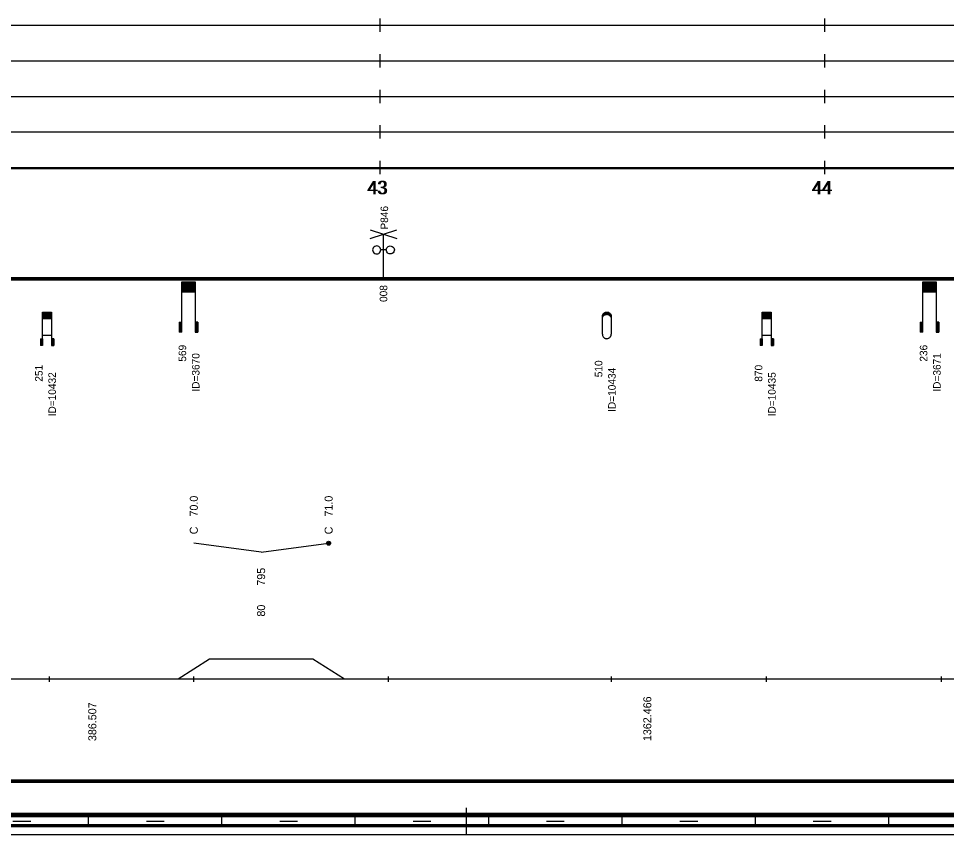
# Model space of a CAD drawing. Extents: x 2 to 10148, y 0 to 380.
# Drawn here: x 4519.3 to 4727.9, y 0 to 183.5 of the extents above; entities that cross this region are included whole.
import ezdxf

# ---------------------------------------------------------------- set-up
doc = ezdxf.new("R2010")
doc.units = 0
for name, color, linetype in [('CARA_S_OBJEKTY', 7, 'Continuous'), ('KRIV1_CARA', 7, 'Continuous'), ('KRIV1_TEXT', 7, 'Continuous'), ('OBJEKTY_TEXT', 7, 'Continuous'), ('OBJEKTY_TVAR', 7, 'Continuous'), ('RAM', 7, 'Continuous'), ('RYCHL_RASTR', 7, 'Continuous'), ('RYCHL_STAN', 7, 'Continuous'), ('STAN_CARA', 7, 'Continuous')]:
    doc.layers.add(name, color=color, linetype=linetype)

msp = doc.modelspace()

# ---------------------------------------------------------------- linework, layer by layer
for p, q in [((4526.17, 35.51), (4526.17, 34.32)), ((4558.59, 35.51), (4558.59, 34.32)), ((4602.42, 35.51), (4602.42, 34.32)), ((4652.55, 35.51), (4652.55, 34.32)), ((4687.39, 35.51), (4687.39, 34.32)), ((4726.73, 35.51), (4726.73, 34.32))]:
    msp.add_line(p, q)
at = {"layer": 'CARA_S_OBJEKTY'}
for p, q in [((4045.76, 125.25), (5128.6, 125.25)), ((4045.76, 125), (5128.6, 125)), ((4045.76, 124.75), (5128.6, 124.75))]:
    msp.add_line(p, q, dxfattribs=at)
at = {"layer": 'KRIV1_CARA'}
for p, q in [((4555.17, 35), (4562.17, 39.53)), ((4562.17, 39.53), (4585.45, 39.53)), ((4585.45, 39.53), (4592.55, 35)), ((4045.76, 35), (5128.6, 35))]:
    msp.add_line(p, q, dxfattribs=at)
at = {"layer": 'KRIV1_TEXT'}
for q in [(4558.67, 65.5), (4589, 65.5)]:
    msp.add_line((4573.81, 63.5), q, dxfattribs=at)
for radius in [0.45, 0.3, 0.15]:
    msp.add_circle((4589, 65.5), radius, dxfattribs=at)
at = {"layer": 'OBJEKTY_TVAR'}
for p, q in [((4598.34, 134), (4604.34, 136)), ((4598.34, 136), (4604.34, 134)), ((4601.34, 125), (4601.34, 135)), ((4598.93, 131.7), (4598.9, 131.46)), ((4599.02, 131.92), (4598.93, 131.7)), ((4599.17, 132.11), (4599.02, 131.92)), ((4599.36, 132.25), (4599.17, 132.11)), ((4599.58, 132.34), (4599.36, 132.25)), ((4599.81, 132.38), (4599.58, 132.34)), ((4600.05, 132.34), (4599.81, 132.38)), ((4600.27, 132.25), (4600.05, 132.34)), ((4600.46, 132.11), (4600.27, 132.25)), ((4600.6, 131.92), (4600.46, 132.11)), ((4600.69, 131.7), (4600.6, 131.92)), ((4600.72, 131.46), (4600.69, 131.7)), ((4601.96, 131.46), (4601.99, 131.7)), ((4601.99, 131.7), (4602.08, 131.92)), ((4602.08, 131.92), (4602.22, 132.11)), ((4602.22, 132.11), (4602.41, 132.25)), ((4602.41, 132.25), (4602.63, 132.34)), ((4602.63, 132.34), (4602.87, 132.38)), ((4602.87, 132.38), (4603.1, 132.34)), ((4603.1, 132.34), (4603.32, 132.25)), ((4603.32, 132.25), (4603.51, 132.11)), ((4603.51, 132.11), (4603.66, 131.92)), ((4603.66, 131.92), (4603.75, 131.7)), ((4603.75, 131.7), (4603.78, 131.46)), ((4598.9, 131.46), (4598.93, 131.23)), ((4598.93, 131.23), (4599.02, 131.01)), ((4599.02, 131.01), (4599.17, 130.82)), ((4599.17, 130.82), (4599.36, 130.67)), ((4599.36, 130.67), (4599.58, 130.58)), ((4599.58, 130.58), (4599.81, 130.55)), ((4599.81, 130.55), (4600.05, 130.58)), ((4600.05, 130.58), (4600.27, 130.67)), ((4600.27, 130.67), (4600.46, 130.82)), ((4600.46, 130.82), (4600.6, 131.01)), ((4600.6, 131.01), (4600.69, 131.23)), ((4600.69, 131.23), (4600.72, 131.46)), ((4601.96, 131.46), (4600.72, 131.46)), ((4601.99, 131.23), (4601.96, 131.46)), ((4602.08, 131.01), (4601.99, 131.23)), ((4602.22, 130.82), (4602.08, 131.01)), ((4602.41, 130.67), (4602.22, 130.82)), ((4602.63, 130.58), (4602.41, 130.67)), ((4602.87, 130.55), (4602.63, 130.58)), ((4603.1, 130.58), (4602.87, 130.55)), ((4603.32, 130.67), (4603.1, 130.58)), ((4603.51, 130.82), (4603.32, 130.67)), ((4603.66, 131.01), (4603.51, 130.82)), ((4603.75, 131.23), (4603.66, 131.01)), ((4603.78, 131.46), (4603.75, 131.23)), ((4555.96, 124.25), (4558.96, 124.25)), ((4555.96, 113), (4555.96, 124.25)), ((4555.96, 124.17), (4558.96, 124.17)), ((4555.96, 124.1), (4558.96, 124.1)), ((4555.96, 124.02), (4558.96, 124.02)), ((4555.96, 123.95), (4558.96, 123.95)), ((4555.96, 123.87), (4558.96, 123.87)), ((4555.96, 123.8), (4558.96, 123.8)), ((4555.96, 123.72), (4558.96, 123.72)), ((4555.96, 123.65), (4558.96, 123.65)), ((4555.96, 123.57), (4558.96, 123.57)), ((4555.96, 123.5), (4558.96, 123.5)), ((4555.96, 123.42), (4558.96, 123.42)), ((4555.96, 123.35), (4558.96, 123.35)), ((4555.96, 123.27), (4558.96, 123.27)), ((4555.96, 123.2), (4558.96, 123.2)), ((4558.96, 124.25), (4558.96, 113)), ((4722.65, 124.25), (4725.65, 124.25)), ((4722.65, 113), (4722.65, 124.25)), ((4722.65, 124.17), (4725.65, 124.17)), ((4722.65, 124.1), (4725.65, 124.1)), ((4722.65, 124.02), (4725.65, 124.02)), ((4722.65, 123.95), (4725.65, 123.95)), ((4722.65, 123.87), (4725.65, 123.87)), ((4722.65, 123.8), (4725.65, 123.8)), ((4722.65, 123.72), (4725.65, 123.72)), ((4722.65, 123.65), (4725.65, 123.65)), ((4722.65, 123.57), (4725.65, 123.57)), ((4722.65, 123.5), (4725.65, 123.5)), ((4722.65, 123.42), (4725.65, 123.42)), ((4722.65, 123.35), (4725.65, 123.35)), ((4722.65, 123.27), (4725.65, 123.27)), ((4722.65, 123.2), (4725.65, 123.2)), ((4725.65, 124.25), (4725.65, 113)), ((4555.96, 123.12), (4558.96, 123.12)), ((4555.96, 123.05), (4558.96, 123.05)), ((4555.96, 122.97), (4558.96, 122.97)), ((4555.96, 122.9), (4558.96, 122.9)), ((4555.96, 122.82), (4558.96, 122.82)), ((4555.96, 122.75), (4558.96, 122.75)), ((4555.96, 122.67), (4558.96, 122.67)), ((4555.96, 122.6), (4558.96, 122.6)), ((4555.96, 122.52), (4558.96, 122.52)), ((4555.96, 122.45), (4558.96, 122.45)), ((4555.96, 122.37), (4558.96, 122.37)), ((4555.96, 122.3), (4558.96, 122.3)), ((4555.96, 122.22), (4558.96, 122.22)), ((4555.96, 122.15), (4558.96, 122.15)), ((4555.96, 122.07), (4558.96, 122.07)), ((4722.65, 123.12), (4725.65, 123.12)), ((4722.65, 123.05), (4725.65, 123.05)), ((4722.65, 122.97), (4725.65, 122.97)), ((4722.65, 122.9), (4725.65, 122.9)), ((4722.65, 122.82), (4725.65, 122.82)), ((4722.65, 122.75), (4725.65, 122.75)), ((4722.65, 122.67), (4725.65, 122.67)), ((4722.65, 122.6), (4725.65, 122.6)), ((4722.65, 122.52), (4725.65, 122.52)), ((4722.65, 122.45), (4725.65, 122.45)), ((4722.65, 122.37), (4725.65, 122.37)), ((4722.65, 122.3), (4725.65, 122.3)), ((4722.65, 122.22), (4725.65, 122.22)), ((4722.65, 122.15), (4725.65, 122.15)), ((4722.65, 122.07), (4725.65, 122.07)), ((4524.67, 110), (4524.67, 117.5)), ((4524.67, 117.5), (4526.67, 117.5)), ((4524.67, 117.45), (4526.67, 117.45)), ((4524.67, 117.4), (4526.67, 117.4)), ((4524.67, 117.35), (4526.67, 117.35)), ((4524.67, 117.3), (4526.67, 117.3)), ((4524.67, 117.25), (4526.67, 117.25)), ((4524.67, 117.2), (4526.67, 117.2)), ((4524.67, 117.15), (4526.67, 117.15)), ((4524.67, 117.1), (4526.67, 117.1)), ((4524.67, 117.05), (4526.67, 117.05)), ((4524.67, 117), (4526.67, 117)), ((4524.67, 116.95), (4526.67, 116.95)), ((4524.67, 116.9), (4526.67, 116.9)), ((4526.67, 117.5), (4526.67, 110)), ((4650.61, 116.81), (4650.67, 116.95)), ((4650.64, 116.9), (4651.18, 116.9)), ((4650.67, 116.95), (4650.73, 117.06)), ((4650.67, 116.95), (4651.33, 116.95)), ((4650.69, 117), (4652.43, 117)), ((4650.72, 117.05), (4652.4, 117.05)), ((4650.73, 117.06), (4650.82, 117.18)), ((4650.76, 117.1), (4652.36, 117.1)), ((4650.8, 117.15), (4652.32, 117.15)), ((4650.82, 117.18), (4650.91, 117.26)), ((4650.85, 117.2), (4652.27, 117.2)), ((4650.9, 117.25), (4652.22, 117.25)), ((4650.91, 117.26), (4651.04, 117.35)), ((4650.96, 117.3), (4652.16, 117.3)), ((4651.03, 117.35), (4652.09, 117.35)), ((4651.04, 117.35), (4651.17, 117.42)), ((4651.04, 116.83), (4651.17, 116.9)), ((4651.12, 117.4), (4652, 117.4)), ((4651.17, 117.42), (4651.2, 117.43)), ((4651.17, 116.9), (4651.2, 116.91)), ((4651.2, 117.43), (4651.32, 117.47)), ((4651.2, 116.91), (4651.32, 116.95)), ((4651.25, 117.45), (4651.87, 117.45)), ((4651.32, 117.47), (4651.46, 117.49)), ((4651.32, 116.95), (4651.46, 116.97)), ((4651.46, 117.49), (4651.57, 117.5)), ((4651.46, 116.97), (4651.57, 116.98)), ((4651.57, 117.5), (4651.7, 117.49)), ((4651.57, 116.98), (4651.7, 116.97)), ((4651.7, 117.49), (4651.83, 117.46)), ((4651.7, 116.97), (4651.83, 116.94)), ((4651.79, 116.95), (4652.45, 116.95)), ((4651.83, 117.46), (4651.94, 117.43)), ((4651.83, 116.94), (4651.94, 116.9)), ((4651.94, 117.43), (4652.05, 117.37)), ((4651.94, 116.9), (4652.48, 116.9)), ((4651.94, 116.9), (4652.05, 116.85)), ((4652.05, 117.37), (4652.12, 117.32)), ((4652.12, 117.32), (4652.27, 117.21)), ((4652.27, 117.21), (4652.35, 117.11)), ((4652.35, 117.11), (4652.44, 116.98)), ((4652.44, 116.98), (4652.48, 116.89)), ((4652.48, 116.89), (4652.52, 116.77)), ((4686.54, 110), (4686.54, 117.5)), ((4686.54, 117.5), (4688.54, 117.5)), ((4686.54, 117.45), (4688.54, 117.45)), ((4686.54, 117.4), (4688.54, 117.4)), ((4686.54, 117.35), (4688.54, 117.35)), ((4686.54, 117.3), (4688.54, 117.3)), ((4686.54, 117.25), (4688.54, 117.25)), ((4686.54, 117.2), (4688.54, 117.2)), ((4686.54, 117.15), (4688.54, 117.15)), ((4686.54, 117.1), (4688.54, 117.1)), ((4686.54, 117.05), (4688.54, 117.05)), ((4686.54, 117), (4688.54, 117)), ((4686.54, 116.95), (4688.54, 116.95)), ((4686.54, 116.9), (4688.54, 116.9)), ((4688.54, 117.5), (4688.54, 110)), ((4524.67, 116.85), (4526.67, 116.85)), ((4524.67, 116.8), (4526.67, 116.8)), ((4524.67, 116.75), (4526.67, 116.75)), ((4524.67, 116.7), (4526.67, 116.7)), ((4524.67, 116.65), (4526.67, 116.65)), ((4524.67, 116.6), (4526.67, 116.6)), ((4524.67, 116.55), (4526.67, 116.55)), ((4524.67, 116.5), (4526.67, 116.5)), ((4524.67, 116.45), (4526.67, 116.45)), ((4524.67, 116.4), (4526.67, 116.4)), ((4524.67, 116.35), (4526.67, 116.35)), ((4524.67, 116.3), (4526.67, 116.3)), ((4524.67, 116.25), (4526.67, 116.25)), ((4524.67, 116.2), (4526.67, 116.2)), ((4524.67, 116.15), (4526.67, 116.15)), ((4524.67, 116.1), (4526.67, 116.1)), ((4524.67, 116.05), (4526.67, 116.05)), ((4555.36, 115.25), (4555.36, 113)), ((4555.36, 115.25), (4555.96, 115.25)), ((4555.43, 115.25), (4555.43, 113)), ((4555.51, 115.25), (4555.51, 113)), ((4555.58, 115.25), (4555.58, 113)), ((4555.66, 115.25), (4555.66, 113)), ((4555.73, 115.25), (4555.73, 113)), ((4555.81, 115.25), (4555.81, 113)), ((4555.88, 115.25), (4555.88, 113)), ((4559.56, 115.25), (4558.96, 115.25)), ((4559.04, 115.25), (4559.04, 113)), ((4559.11, 115.25), (4559.11, 113)), ((4559.19, 115.25), (4559.19, 113)), ((4559.26, 115.25), (4559.26, 113)), ((4559.34, 115.25), (4559.34, 113)), ((4559.41, 115.25), (4559.41, 113)), ((4559.49, 115.25), (4559.49, 113)), ((4559.56, 115.25), (4559.56, 113)), ((4650.56, 116.5), (4650.57, 116.65)), ((4650.56, 116.55), (4650.74, 116.55)), ((4650.56, 112.5), (4650.56, 116.5)), ((4650.56, 116.5), (4650.71, 116.5)), ((4650.56, 116.45), (4650.68, 116.45)), ((4650.56, 116.4), (4650.65, 116.4)), ((4650.56, 116.35), (4650.63, 116.35)), ((4650.56, 116.3), (4650.61, 116.3)), ((4650.56, 116.25), (4650.6, 116.25)), ((4650.56, 116.2), (4650.59, 116.2)), ((4650.56, 116.15), (4650.58, 116.15)), ((4650.56, 115.98), (4650.57, 116.13)), ((4650.56, 116.1), (4650.57, 116.1)), ((4650.57, 116.65), (4650.61, 116.81)), ((4650.57, 116.65), (4650.82, 116.65)), ((4650.57, 116.6), (4650.78, 116.6)), ((4650.57, 116.13), (4650.61, 116.28)), ((4650.58, 116.7), (4650.87, 116.7)), ((4650.59, 116.75), (4650.93, 116.75)), ((4650.61, 116.8), (4650.99, 116.8)), ((4650.61, 116.28), (4650.67, 116.43)), ((4650.62, 116.85), (4651.07, 116.85)), ((4650.67, 116.43), (4650.73, 116.53)), ((4650.73, 116.53), (4650.82, 116.65)), ((4650.82, 116.65), (4650.91, 116.74)), ((4650.91, 116.74), (4651.04, 116.83)), ((4652.05, 116.85), (4652.5, 116.85)), ((4652.05, 116.85), (4652.12, 116.8)), ((4652.12, 116.8), (4652.27, 116.68)), ((4652.13, 116.8), (4652.51, 116.8)), ((4652.19, 116.75), (4652.53, 116.75)), ((4652.25, 116.7), (4652.54, 116.7)), ((4652.27, 116.68), (4652.35, 116.59)), ((4652.3, 116.65), (4652.55, 116.65)), ((4652.34, 116.6), (4652.55, 116.6)), ((4652.35, 116.59), (4652.44, 116.46)), ((4652.38, 116.55), (4652.56, 116.55)), ((4652.41, 116.5), (4652.56, 116.5)), ((4652.44, 116.46), (4652.48, 116.37)), ((4652.44, 116.45), (4652.56, 116.45)), ((4652.47, 116.4), (4652.56, 116.4)), ((4652.48, 116.37), (4652.52, 116.24)), ((4652.49, 116.35), (4652.56, 116.35)), ((4652.51, 116.3), (4652.56, 116.3)), ((4652.52, 116.77), (4652.55, 116.65)), ((4652.52, 116.25), (4652.56, 116.25)), ((4652.52, 116.24), (4652.55, 116.13)), ((4652.53, 116.2), (4652.56, 116.2)), ((4652.54, 116.15), (4652.56, 116.15)), ((4652.55, 116.65), (4652.56, 116.56)), ((4652.55, 116.13), (4652.56, 116.03)), ((4652.55, 116.1), (4652.56, 116.1)), ((4652.56, 116.56), (4652.56, 116.5)), ((4652.56, 116.5), (4652.56, 112.5)), ((4652.56, 116.03), (4652.56, 115.98)), ((4686.54, 116.85), (4688.54, 116.85)), ((4686.54, 116.8), (4688.54, 116.8)), ((4686.54, 116.75), (4688.54, 116.75)), ((4686.54, 116.7), (4688.54, 116.7)), ((4686.54, 116.65), (4688.54, 116.65)), ((4686.54, 116.6), (4688.54, 116.6)), ((4686.54, 116.55), (4688.54, 116.55)), ((4686.54, 116.5), (4688.54, 116.5)), ((4686.54, 116.45), (4688.54, 116.45)), ((4686.54, 116.4), (4688.54, 116.4)), ((4686.54, 116.35), (4688.54, 116.35)), ((4686.54, 116.3), (4688.54, 116.3)), ((4686.54, 116.25), (4688.54, 116.25)), ((4686.54, 116.2), (4688.54, 116.2)), ((4686.54, 116.15), (4688.54, 116.15)), ((4686.54, 116.1), (4688.54, 116.1)), ((4686.54, 116.05), (4688.54, 116.05)), ((4722.05, 115.25), (4722.05, 113)), ((4722.05, 115.25), (4722.65, 115.25)), ((4722.12, 115.25), (4722.12, 113)), ((4722.2, 115.25), (4722.2, 113)), ((4722.27, 115.25), (4722.27, 113)), ((4722.35, 115.25), (4722.35, 113)), ((4722.42, 115.25), (4722.42, 113)), ((4722.5, 115.25), (4722.5, 113)), ((4722.57, 115.25), (4722.57, 113)), ((4726.25, 115.25), (4725.65, 115.25)), ((4725.73, 115.25), (4725.73, 113)), ((4725.8, 115.25), (4725.8, 113)), ((4725.88, 115.25), (4725.88, 113)), ((4725.95, 115.25), (4725.95, 113)), ((4726.03, 115.25), (4726.03, 113)), ((4726.1, 115.25), (4726.1, 113)), ((4726.18, 115.25), (4726.18, 113)), ((4726.25, 115.25), (4726.25, 113)), ((4555.96, 113), (4555.36, 113)), ((4558.96, 113), (4559.56, 113)), ((4722.65, 113), (4722.05, 113)), ((4725.65, 113), (4726.25, 113)), ((4524.17, 111.5), (4524.67, 111.5)), ((4524.17, 111.5), (4524.17, 110)), ((4524.22, 111.5), (4524.22, 110)), ((4524.27, 111.5), (4524.27, 110)), ((4524.32, 111.5), (4524.32, 110)), ((4524.37, 111.5), (4524.37, 110)), ((4524.42, 111.5), (4524.42, 110)), ((4524.47, 111.5), (4524.47, 110)), ((4524.52, 111.5), (4524.52, 110)), ((4524.57, 111.5), (4524.57, 110)), ((4524.62, 111.5), (4524.62, 110)), ((4524.67, 112.31), (4526.67, 112.31)), ((4527.17, 111.5), (4526.67, 111.5)), ((4526.72, 111.5), (4526.72, 110)), ((4526.77, 111.5), (4526.77, 110)), ((4526.82, 111.5), (4526.82, 110)), ((4526.87, 111.5), (4526.87, 110)), ((4526.92, 111.5), (4526.92, 110)), ((4526.97, 111.5), (4526.97, 110)), ((4527.02, 111.5), (4527.02, 110)), ((4527.07, 111.5), (4527.07, 110)), ((4527.12, 111.5), (4527.12, 110)), ((4527.17, 111.5), (4527.17, 110)), ((4650.56, 112.5), (4650.57, 112.35)), ((4650.57, 112.35), (4650.61, 112.2)), ((4650.61, 112.2), (4650.67, 112.05)), ((4650.67, 112.05), (4650.73, 111.95)), ((4650.73, 111.95), (4650.82, 111.83)), ((4650.82, 111.83), (4650.91, 111.74)), ((4650.91, 111.74), (4651.04, 111.65)), ((4651.04, 111.65), (4651.17, 111.58)), ((4651.17, 111.58), (4651.2, 111.57)), ((4651.2, 111.57), (4651.32, 111.53)), ((4651.32, 111.53), (4651.46, 111.51)), ((4651.46, 111.51), (4651.57, 111.5)), ((4651.57, 111.5), (4651.7, 111.51)), ((4651.7, 111.51), (4651.83, 111.54)), ((4651.83, 111.54), (4651.94, 111.58)), ((4651.94, 111.58), (4652.05, 111.63)), ((4652.05, 111.63), (4652.12, 111.68)), ((4652.12, 111.68), (4652.27, 111.8)), ((4652.27, 111.8), (4652.35, 111.9)), ((4652.35, 111.9), (4652.44, 112.02)), ((4652.44, 112.02), (4652.48, 112.11)), ((4652.48, 112.11), (4652.52, 112.24)), ((4652.52, 112.24), (4652.55, 112.35)), ((4652.55, 112.35), (4652.56, 112.45)), ((4652.56, 112.45), (4652.56, 112.5)), ((4686.04, 111.5), (4686.54, 111.5)), ((4686.04, 111.5), (4686.04, 110)), ((4686.09, 111.5), (4686.09, 110)), ((4686.14, 111.5), (4686.14, 110)), ((4686.19, 111.5), (4686.19, 110)), ((4686.24, 111.5), (4686.24, 110)), ((4686.29, 111.5), (4686.29, 110)), ((4686.34, 111.5), (4686.34, 110)), ((4686.39, 111.5), (4686.39, 110)), ((4686.44, 111.5), (4686.44, 110)), ((4686.49, 111.5), (4686.49, 110)), ((4686.54, 112.31), (4688.54, 112.31)), ((4689.04, 111.5), (4688.54, 111.5)), ((4688.59, 111.5), (4688.59, 110)), ((4688.64, 111.5), (4688.64, 110)), ((4688.69, 111.5), (4688.69, 110)), ((4688.74, 111.5), (4688.74, 110)), ((4688.79, 111.5), (4688.79, 110)), ((4688.84, 111.5), (4688.84, 110)), ((4688.89, 111.5), (4688.89, 110)), ((4688.94, 111.5), (4688.94, 110)), ((4688.99, 111.5), (4688.99, 110)), ((4689.04, 111.5), (4689.04, 110)), ((4524.67, 110), (4524.17, 110)), ((4526.67, 110), (4527.17, 110)), ((4686.54, 110), (4686.04, 110)), ((4688.54, 110), (4689.04, 110))]:
    msp.add_line(p, q, dxfattribs=at)
at = {"layer": 'RAM'}
for p, q in [((4045.76, 4.75), (5128.6, 4.75)), ((4045.76, 4.5), (5128.6, 4.5)), ((4045.76, 4.25), (5128.6, 4.25)), ((4620, 0), (4620, 6)), ((4045.76, 4), (5128.6, 4)), ((4045.76, 2.25), (5128.6, 2.25)), ((4518, 3), (4522, 3)), ((4535, 2), (4535, 4)), ((4548, 3), (4552, 3)), ((4565, 2), (4565, 4)), ((4578, 3), (4582, 3)), ((4595, 2), (4595, 4)), ((4608, 3), (4612, 3)), ((4625, 2), (4625, 4)), ((4638, 3), (4642, 3)), ((4655, 2), (4655, 4)), ((4668, 3), (4672, 3)), ((4685, 2), (4685, 4)), ((4698, 3), (4702, 3)), ((4715, 2), (4715, 4)), ((4045.76, 2), (5128.6, 2)), ((4045.76, 1.75), (5128.6, 1.75)), ((4045.76, 0), (5128.6, 0))]:
    msp.add_line(p, q, dxfattribs=at)
at = {"layer": 'RYCHL_RASTR'}
for p, q in [((4041.69, 182), (5128.21, 182)), ((4600.57, 180.5), (4600.57, 183.5)), ((4700.57, 180.5), (4700.57, 183.5)), ((4600.57, 172.5), (4600.57, 175.5)), ((4700.57, 172.5), (4700.57, 175.5)), ((4041.64, 174), (5128.26, 174)), ((4600.57, 164.5), (4600.57, 167.5)), ((4700.57, 164.5), (4700.57, 167.5)), ((4041.69, 166), (5128.25, 166)), ((4600.57, 156.5), (4600.57, 159.5)), ((4700.57, 156.5), (4700.57, 159.5)), ((4041.65, 158), (5128.24, 158)), ((4600.57, 148.5), (4600.57, 151.5)), ((4700.57, 148.5), (4700.57, 151.5)), ((4045.76, 150), (5128.6, 150)), ((4045.76, 149.75), (5128.6, 149.75))]:
    msp.add_line(p, q, dxfattribs=at)
at = {"layer": 'STAN_CARA'}
for p, q in [((4302.07, 12.25), (4799.07, 12.25)), ((4302.07, 12), (4799.07, 12)), ((4302.07, 12), (4799.07, 12)), ((4302.07, 11.75), (4799.07, 11.75))]:
    msp.add_line(p, q, dxfattribs=at)

# ---------------------------------------------------------------- texts
at = {"layer": 'KRIV1_TEXT'}
for s, p in [('70.0', (4559.57, 71.5)), ('71.0', (4589.9, 71.5)), ('C', (4559.57, 67.5)), ('C', (4589.9, 67.5)), ('795', (4574.71, 55.95)), ('80', (4574.71, 49)), ('386.507', (4536.75, 21)), ('1362.466', (4661.57, 21))]:
    msp.add_text(s, height=1.8, rotation=90, dxfattribs=at).set_placement(p)
at = {"layer": 'OBJEKTY_TEXT'}
for s, p in [('P846', (4602.38, 136.04)), ('008', (4602.19, 119.76)), ('569', (4556.96, 106.33)), ('236', (4723.65, 106.33)), ('ID=3670', (4559.96, 99.59)), ('510', (4650.56, 102.83)), ('ID=3671', (4726.65, 99.59)), ('251', (4524.67, 101.83)), ('ID=10434', (4653.56, 95.03)), ('870', (4686.54, 101.83)), ('ID=10432', (4527.67, 94.03)), ('ID=10435', (4689.54, 94.03))]:
    msp.add_text(s, height=1.7, rotation=90, dxfattribs=at).set_placement(p)
at = {"layer": 'RYCHL_STAN'}
for s, p in [('43', (4597.63, 144)), ('43', (4597.88, 144)), ('44', (4697.63, 144)), ('44', (4697.88, 144))]:
    msp.add_text(s, height=3, dxfattribs=at).set_placement(p)

doc.saveas('drawing.dxf')
